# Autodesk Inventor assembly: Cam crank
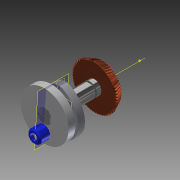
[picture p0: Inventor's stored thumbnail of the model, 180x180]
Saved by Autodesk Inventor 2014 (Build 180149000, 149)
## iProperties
Created: 2008-07
Part Number: Cam crank
Document SubType Name: Assembly
Designer: tangg
Mass: 210.119 g
Surface Area: 145.448 cm^2
Volume: 32.7179 cm^3
Density: 6.42214 g/cm^3
Author: tangg
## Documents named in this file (6)
- C:\Users\iTools\Desktop\tutorial files\Dynamic Simulation 1 and 2\Cam crank.iam
- C:\Users\iTools\Desktop\tutorial files\Dynamic Simulation 1 and 2\Crank shaft.ipt
- C:\Users\iTools\Desktop\tutorial files\Dynamic Simulation 1 and 2\Roller.ipt
- C:\Users\iTools\Desktop\tutorial files\Dynamic Simulation 1 and 2\Eccentric.ipt
- C:\Users\iTools\Desktop\tutorial files\Dynamic Simulation 1 and 2\Bevel Gear21.ipt
- C:\Users\iTools\Desktop\tutorial files\Dynamic Simulation 1 and 2\Cam  lobe.ipt
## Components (5 placed, 5 different names)
1. Crank shaft:1 — Flush:1, Mate:4, Mate:7, Mate:8, Flush:3, Mate:9
2. Roller:1 — Mate:2, Mate:3
3. Eccentric:1 — Mate:2, Mate:3, Flush:1, Mate:4, Mate:10
4. Bevel Gear2:1 — Mate:8, Flush:3
5. Cam  lobe:1 — Mate:9, Mate:10
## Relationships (9: Mate 7, Flush 2)
- Mate:2: Roller:1 ↔ Eccentric:1
- Mate:3: Roller:1 ↔ Eccentric:1
- Flush:1: Crank shaft:1 ↔ Eccentric:1
- Mate:4: Crank shaft:1 ↔ Eccentric:1
- Mate:7: Crank shaft:1
- Mate:8: Crank shaft:1 ↔ Bevel Gear2:1
- Flush:3: Crank shaft:1 ↔ Bevel Gear2:1
- Mate:9: Crank shaft:1 ↔ Cam  lobe:1
- Mate:10: Eccentric:1 ↔ Cam  lobe:1
